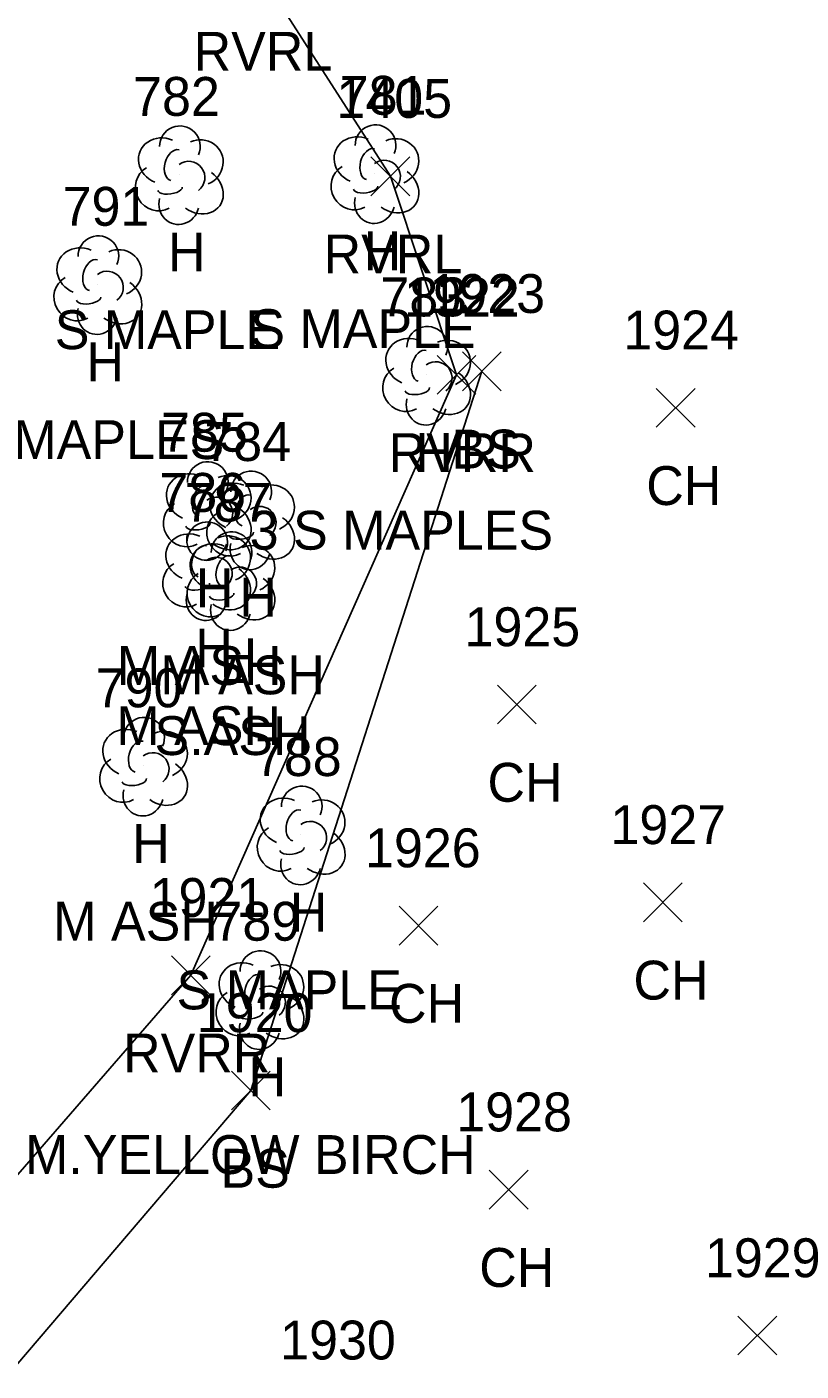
# Model space of a CAD drawing. Extents: x 1545627 to 1546562, y 571176 to 576667.
# Drawn here: x 1546246.9 to 1546286.7, y 572339.9 to 572409 of the extents above; entities that cross this region are included whole.
import ezdxf

# ---------------------------------------------------------------- set-up
doc = ezdxf.new("R2010")
doc.units = 0
for name, color, linetype in [('L_A', 7, 'Continuous'), ('L_C', 7, 'Continuous'), ('L_I', 7, 'Continuous'), ('L_TIC', 7, 'Continuous'), ('LAWE', 7, 'Continuous'), ('LELB', 7, 'Continuous'), ('LTD', 7, 'Continuous')]:
    doc.layers.add(name, color=color, linetype=linetype)

msp = doc.modelspace()

# ---------------------------------------------------------------- linework, layer by layer
at = {"layer": 'L_TIC'}
for points in [[(1546264.558, 572400.332), (1546266.558, 572402.332)], [(1546266.558, 572400.332), (1546264.558, 572402.332)], [(1546267.959, 572390.116), (1546269.959, 572392.116)], [(1546269.959, 572390.116), (1546267.959, 572392.116)], [(1546269.264, 572390.299), (1546271.264, 572392.299)], [(1546271.264, 572390.299), (1546269.264, 572392.299)], [(1546279.236, 572388.421), (1546281.236, 572390.421)], [(1546281.236, 572388.421), (1546279.236, 572390.421)], [(1546271.067, 572373.159), (1546273.067, 572375.159)], [(1546273.067, 572373.159), (1546271.067, 572375.159)], [(1546278.575, 572362.983), (1546280.575, 572364.983)], [(1546280.575, 572362.983), (1546278.575, 572364.983)], [(1546266.004, 572361.788), (1546268.004, 572363.788)], [(1546268.004, 572361.788), (1546266.004, 572363.788)], [(1546254.297, 572359.235), (1546256.297, 572361.235)], [(1546256.297, 572359.235), (1546254.297, 572361.235)], [(1546257.38, 572353.309), (1546259.38, 572355.309)], [(1546259.38, 572353.309), (1546257.38, 572355.309)], [(1546270.643, 572348.205), (1546272.643, 572350.205)], [(1546272.643, 572348.205), (1546270.643, 572350.205)], [(1546283.443, 572340.705), (1546285.443, 572342.705)], [(1546285.443, 572340.705), (1546283.443, 572342.705)]]:
    msp.add_lwpolyline(points, dxfattribs=at)
at = {"layer": 'LAWE'}
for points in [[(1546133.748, 572533.357), (1546159.974, 572504.858), (1546191.946, 572477.2), (1546228.308, 572454.44), (1546258.871, 572411.758), (1546265.558, 572401.332)], [(1546268.959, 572391.116), (1546265.558, 572401.332)], [(1546079.438, 571966.947), (1546077.788, 571985.488), (1546075.176, 572034.738), (1546072.514, 572073.367), (1546072.957, 572091.545), (1546079.326, 572109.636), (1546089.965, 572133.875), (1546098.205, 572146.168), (1546103.269, 572146.803), (1546106.386, 572149.622), (1546130.143, 572181.263), (1546136.759, 572192.153), (1546140.729, 572200.768), (1546161.621, 572243.317), (1546187.565, 572282.786), (1546232.645, 572334.154), (1546255.297, 572360.235), (1546268.959, 572391.116)]]:
    msp.add_lwpolyline(points, dxfattribs=at)
at = {"layer": 'LELB'}
msp.add_lwpolyline([(1546140.457, 572188.687), (1546144.086, 572197.302), (1546164.869, 572240.482), (1546191.763, 572281.913), (1546238.283, 572330.782), (1546258.38, 572354.309), (1546270.264, 572391.299)], dxfattribs=at)
at = {"layer": 'LTD'}
for p, q in [((1546264.75, 572401.494), (1546264.75, 572401.494)), ((1546264.75, 572401.494), (1546264.75, 572401.494)), ((1546254.687, 572401.438), (1546254.687, 572401.438)), ((1546254.687, 572401.438), (1546254.687, 572401.438)), ((1546250.492, 572395.785), (1546250.492, 572395.785)), ((1546250.492, 572395.785), (1546250.492, 572395.785)), ((1546267.408, 572391.125), (1546267.408, 572391.125)), ((1546267.408, 572391.125), (1546267.408, 572391.125)), ((1546256.121, 572384.166), (1546256.121, 572384.166)), ((1546256.121, 572384.166), (1546256.121, 572384.166)), ((1546258.352, 572383.685), (1546258.352, 572383.685)), ((1546258.352, 572383.685), (1546258.352, 572383.685)), ((1546256.093, 572381.07), (1546256.093, 572381.07)), ((1546256.093, 572381.07), (1546256.093, 572381.07)), ((1546257.345, 572380.561), (1546257.345, 572380.561)), ((1546257.345, 572380.561), (1546257.345, 572380.561)), ((1546252.845, 572371.017), (1546252.845, 572371.017)), ((1546252.845, 572371.017), (1546252.845, 572371.017)), ((1546260.953, 572367.48), (1546260.953, 572367.48)), ((1546260.953, 572367.48), (1546260.953, 572367.48)), ((1546258.831, 572359.013), (1546258.831, 572359.013)), ((1546258.831, 572359.013), (1546258.831, 572359.013))]:
    msp.add_line(p, q, dxfattribs=at)
for centre in [(1546254.734, 572402.872), (1546264.796, 572402.928), (1546250.539, 572397.219), (1546267.455, 572392.559), (1546256.168, 572385.6), (1546258.398, 572385.119), (1546256.14, 572382.504), (1546257.392, 572381.995), (1546252.892, 572372.451), (1546261, 572368.914), (1546258.878, 572360.447)]:
    msp.add_arc(centre, 1.047, 335.52715, 180.95627, dxfattribs=at)
for centre, major_axis, ratio, start_param, end_param in [((1546263.958, 572402.16), (1.21, -0.512), 0.895232, 1.570796, 4.712389), ((1546253.896, 572402.105), (1.21, -0.512), 0.895232, 1.570796, 4.712389), ((1546255.729, 572402.022), (-1.141, -0.483), 0.949671, 1.570796, 4.712389), ((1546265.791, 572402.077), (-1.141, -0.483), 0.949671, 1.570796, 4.712389), ((1546254.479, 572401.897), (-0.208, -0.792), 0.645439, 3.141593, 6.283185), ((1546255.188, 572401.272), (-0.5, 0.667), 0.989748, 3.141593, 6.283185), ((1546264.541, 572401.952), (-0.208, -0.792), 0.645439, 3.141593, 6.283185), ((1546265.25, 572401.327), (-0.5, 0.667), 0.989748, 3.141593, 6.283185), ((1546253.604, 572400.73), (0.584, -1.042), 0.959034, 3.141593, 6.283185), ((1546255.688, 572400.605), (-1.09, 0.792), 0.841452, 1.570796, 4.712389), ((1546263.666, 572400.785), (0.584, -1.042), 0.959034, 3.141593, 6.283185), ((1546265.75, 572400.66), (-1.09, 0.792), 0.841452, 1.570796, 4.712389), ((1546254.229, 572400.688), (-0.625, -0.083), 0.423636, 0, 3.141593), ((1546264.291, 572400.744), (-0.625, -0.083), 0.423636, 0, 3.141593), ((1546254.688, 572399.938), (0.265, 1.061), 0.942809, 1.570796, 4.712389), ((1546264.75, 572399.994), (0.265, 1.061), 0.942809, 1.570796, 4.712389), ((1546249.701, 572396.451), (1.21, -0.512), 0.895232, 1.570796, 4.712389), ((1546251.534, 572396.368), (-1.141, -0.483), 0.949671, 1.570796, 4.712389), ((1546250.284, 572396.243), (-0.208, -0.792), 0.645439, 3.141593, 6.283185), ((1546249.409, 572395.076), (0.584, -1.042), 0.959034, 3.141593, 6.283185), ((1546250.993, 572395.618), (-0.5, 0.667), 0.989748, 3.141593, 6.283185), ((1546251.493, 572394.952), (-1.09, 0.792), 0.841452, 1.570796, 4.712389), ((1546250.493, 572394.285), (0.265, 1.061), 0.942809, 1.570796, 4.712389), ((1546250.034, 572395.035), (-0.625, -0.083), 0.423636, 0, 3.141593), ((1546266.616, 572391.792), (1.21, -0.512), 0.895232, 1.570796, 4.712389), ((1546268.45, 572391.709), (-1.141, -0.483), 0.949671, 1.570796, 4.712389), ((1546267.2, 572391.583), (-0.208, -0.792), 0.645439, 3.141593, 6.283185), ((1546267.908, 572390.958), (-0.5, 0.667), 0.989748, 3.141593, 6.283185), ((1546266.325, 572390.416), (0.584, -1.042), 0.959034, 3.141593, 6.283185), ((1546268.408, 572390.292), (-1.09, 0.792), 0.841452, 1.570796, 4.712389), ((1546266.95, 572390.375), (-0.625, -0.083), 0.423636, 0, 3.141593), ((1546267.408, 572389.625), (0.265, 1.061), 0.942809, 1.570796, 4.712389), ((1546255.329, 572384.832), (1.21, -0.512), 0.895232, 1.570796, 4.712389), ((1546257.56, 572384.352), (1.21, -0.512), 0.895232, 1.570796, 4.712389), ((1546257.163, 572384.749), (-1.141, -0.483), 0.949671, 1.570796, 4.712389), ((1546259.393, 572384.269), (-1.141, -0.483), 0.949671, 1.570796, 4.712389), ((1546255.913, 572384.624), (-0.208, -0.792), 0.645439, 3.141593, 6.283185), ((1546256.621, 572383.999), (-0.5, 0.667), 0.989748, 3.141593, 6.283185), ((1546258.143, 572384.144), (-0.208, -0.792), 0.645439, 3.141593, 6.283185), ((1546255.038, 572383.457), (0.584, -1.042), 0.959034, 3.141593, 6.283185), ((1546257.121, 572383.333), (-1.09, 0.792), 0.841452, 1.570796, 4.712389), ((1546258.852, 572383.519), (-0.5, 0.667), 0.989748, 3.141593, 6.283185), ((1546255.663, 572383.416), (-0.625, -0.083), 0.423636, 0, 3.141593), ((1546257.268, 572382.977), (0.584, -1.042), 0.959034, 3.141593, 6.283185), ((1546259.352, 572382.852), (-1.09, 0.792), 0.841452, 1.570796, 4.712389), ((1546255.301, 572381.736), (1.21, -0.512), 0.895232, 1.570796, 4.712389), ((1546256.121, 572382.666), (0.265, 1.061), 0.942809, 1.570796, 4.712389), ((1546257.135, 572381.653), (-1.141, -0.483), 0.949671, 1.570796, 4.712389), ((1546257.893, 572382.935), (-0.625, -0.083), 0.423636, 0, 3.141593), ((1546256.553, 572381.228), (1.21, -0.512), 0.895232, 1.570796, 4.712389), ((1546255.885, 572381.528), (-0.208, -0.792), 0.645439, 3.141593, 6.283185), ((1546258.352, 572382.185), (0.265, 1.061), 0.942809, 1.570796, 4.712389), ((1546258.386, 572381.145), (-1.141, -0.483), 0.949671, 1.570796, 4.712389), ((1546255.01, 572380.361), (0.584, -1.042), 0.959034, 3.141593, 6.283185), ((1546256.593, 572380.903), (-0.5, 0.667), 0.989748, 3.141593, 6.283185), ((1546257.136, 572381.02), (-0.208, -0.792), 0.645439, 3.141593, 6.283185), ((1546256.262, 572379.853), (0.584, -1.042), 0.959034, 3.141593, 6.283185), ((1546257.093, 572380.236), (-1.09, 0.792), 0.841452, 1.570796, 4.712389), ((1546257.845, 572380.395), (-0.5, 0.667), 0.989748, 3.141593, 6.283185), ((1546255.635, 572380.32), (-0.625, -0.083), 0.423636, 0, 3.141593), ((1546258.345, 572379.728), (-1.09, 0.792), 0.841452, 1.570796, 4.712389), ((1546256.093, 572379.57), (0.265, 1.061), 0.942809, 1.570796, 4.712389), ((1546256.887, 572379.811), (-0.625, -0.083), 0.423636, 0, 3.141593), ((1546257.345, 572379.061), (0.265, 1.061), 0.942809, 1.570796, 4.712389), ((1546252.054, 572371.684), (1.21, -0.512), 0.895232, 1.570796, 4.712389), ((1546253.887, 572371.601), (-1.141, -0.483), 0.949671, 1.570796, 4.712389), ((1546252.637, 572371.476), (-0.208, -0.792), 0.645439, 3.141593, 6.283185), ((1546253.346, 572370.851), (-0.5, 0.667), 0.989748, 3.141593, 6.283185), ((1546251.762, 572370.309), (0.584, -1.042), 0.959034, 3.141593, 6.283185), ((1546253.846, 572370.184), (-1.09, 0.792), 0.841452, 1.570796, 4.712389), ((1546252.387, 572370.267), (-0.625, -0.083), 0.423636, 0, 3.141593), ((1546252.846, 572369.517), (0.265, 1.061), 0.942809, 1.570796, 4.712389), ((1546260.161, 572368.147), (1.21, -0.512), 0.895232, 1.570796, 4.712389), ((1546261.995, 572368.064), (-1.141, -0.483), 0.949671, 1.570796, 4.712389), ((1546260.745, 572367.939), (-0.208, -0.792), 0.645439, 3.141593, 6.283185), ((1546259.87, 572366.772), (0.584, -1.042), 0.959034, 3.141593, 6.283185), ((1546261.453, 572367.314), (-0.5, 0.667), 0.989748, 3.141593, 6.283185), ((1546261.953, 572366.647), (-1.09, 0.792), 0.841452, 1.570796, 4.712389), ((1546260.953, 572365.98), (0.265, 1.061), 0.942809, 1.570796, 4.712389), ((1546260.495, 572366.73), (-0.625, -0.083), 0.423636, 0, 3.141593), ((1546258.039, 572359.679), (1.21, -0.512), 0.895232, 1.570796, 4.712389), ((1546259.873, 572359.596), (-1.141, -0.483), 0.949671, 1.570796, 4.712389), ((1546258.623, 572359.471), (-0.208, -0.792), 0.645439, 3.141593, 6.283185), ((1546257.748, 572358.304), (0.584, -1.042), 0.959034, 3.141593, 6.283185), ((1546259.331, 572358.846), (-0.5, 0.667), 0.989748, 3.141593, 6.283185), ((1546259.831, 572358.179), (-1.09, 0.792), 0.841452, 1.570796, 4.712389), ((1546258.373, 572358.262), (-0.625, -0.083), 0.423636, 0, 3.141593), ((1546258.832, 572357.513), (0.265, 1.061), 0.942809, 1.570796, 4.712389)]:
    msp.add_ellipse(centre, major_axis=major_axis, ratio=ratio, start_param=start_param, end_param=end_param, dxfattribs=at)

# ---------------------------------------------------------------- texts
at = {"layer": 'L_A'}
for s, p in [('RVRL', (1546255.438, 572406.758)), ('H', (1546254.121, 572396.438)), ('RVRL', (1546262.125, 572396.332)), ('H', (1546264.183, 572396.494)), ('H', (1546249.926, 572390.785)), ('BS', (1546268.705, 572386.299)), ('RVRR', (1546265.471, 572386.116)), ('H', (1546266.841, 572386.125)), ('CH', (1546278.724, 572384.421)), ('H', (1546255.554, 572379.166)), ('H', (1546257.785, 572378.685)), ('H', (1546255.526, 572376.07)), ('H', (1546256.778, 572375.561)), ('CH', (1546270.555, 572369.159)), ('H', (1546252.279, 572366.017)), ('H', (1546260.386, 572362.48)), ('CH', (1546278.063, 572358.983)), ('CH', (1546265.492, 572357.788)), ('RVRR', (1546251.809, 572355.235)), ('H', (1546258.264, 572354.013)), ('BS', (1546256.821, 572349.309)), ('CH', (1546270.131, 572344.205))]:
    msp.add_text(s, height=2, dxfattribs=at).set_placement(p)
at = {"layer": 'L_C'}
for s, p in [('S MAPLE', (1546248.294, 572392.438)), ('S MAPLE', (1546258.356, 572392.494)), ('3 S MAPLES', (1546241.406, 572386.785)), ('3 S MAPLES', (1546258.322, 572382.125)), ('M ASH', (1546251.491, 572375.166)), ('M ASH', (1546253.722, 572374.685)), ('M ASH', (1546251.463, 572372.07)), ('S.ASH', (1546253.424, 572371.561)), ('M ASH', (1546248.216, 572362.017)), ('S MAPLE', (1546254.559, 572358.48)), ('M.YELLOW BIRCH', (1546246.768, 572350.013))]:
    msp.add_text(s, height=2, dxfattribs=at).set_placement(p)
at = {"layer": 'L_I'}
for s, p in [('782', (1546252.325, 572404.438)), ('1405', (1546262.786, 572404.332)), ('781', (1546262.954, 572404.494)), ('791', (1546248.697, 572398.785)), ('783', (1546265.046, 572394.125)), ('1922', (1546266.266, 572394.116)), ('1923', (1546267.571, 572394.299)), ('1924', (1546277.543, 572392.421)), ('785', (1546253.759, 572387.166)), ('784', (1546255.989, 572386.685)), ('786', (1546253.676, 572384.07)), ('787', (1546254.983, 572383.561)), ('1925', (1546269.374, 572377.159)), ('790', (1546250.397, 572374.017)), ('788', (1546258.591, 572370.48)), ('1927', (1546276.882, 572366.983)), ('1926', (1546264.256, 572365.788)), ('1921', (1546253.171, 572363.235)), ('789', (1546256.461, 572362.013)), ('1920', (1546255.601, 572357.309)), ('1928', (1546268.95, 572352.205)), ('1929', (1546281.742, 572344.705)), ('1930', (1546259.89, 572340.472))]:
    msp.add_text(s, height=2, dxfattribs=at).set_placement(p)

doc.saveas('drawing.dxf')
